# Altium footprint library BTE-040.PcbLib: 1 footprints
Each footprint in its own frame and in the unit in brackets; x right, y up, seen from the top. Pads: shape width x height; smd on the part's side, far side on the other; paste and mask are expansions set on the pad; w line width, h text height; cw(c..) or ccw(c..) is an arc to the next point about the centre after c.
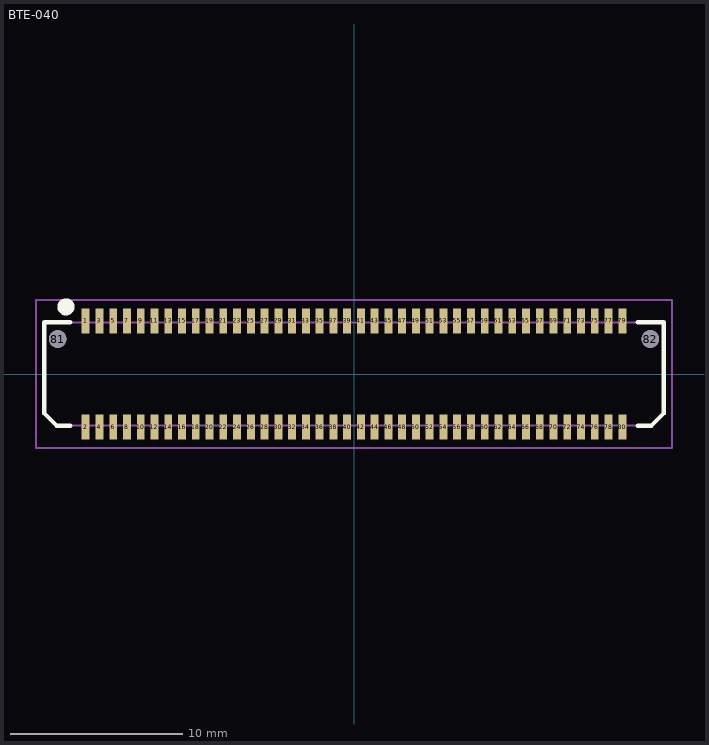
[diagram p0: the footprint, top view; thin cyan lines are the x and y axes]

## BTE-040 [mm] "0.8mm Samtech socket"
height 4.27
pads (82):
  rect 0.46x1.45 smd: 1(-15.6,3.085) 2(-15.6,-3.085) 3(-14.8,3.085) 4(-14.8,-3.085) 5(-14,3.085) 6(-14,-3.085) 7(-13.2,3.085) 8(-13.2,-3.085) 9(-12.4,3.085) 10(-12.4,-3.085) 11(-11.6,3.085) 12(-11.6,-3.085) 13(-10.8,3.085) 14(-10.8,-3.085) 15(-10,3.085) 16(-10,-3.085) 17(-9.2,3.085) 18(-9.2,-3.085) 19(-8.4,3.085) 20(-8.4,-3.085) 21(-7.6,3.085) 22(-7.6,-3.085) 23(-6.8,3.085) 24(-6.8,-3.085) 25(-6,3.085) 26(-6,-3.085) 27(-5.2,3.085) 28(-5.2,-3.085) 29(-4.4,3.085) 30(-4.4,-3.085) 31(-3.6,3.085) 32(-3.6,-3.085) 33(-2.8,3.085) 34(-2.8,-3.085) 35(-2,3.085) 36(-2,-3.085) 37(-1.2,3.085) 38(-1.2,-3.085) 39(-0.4,3.085) 40(-0.4,-3.085) 41(0.4,3.085) 42(0.4,-3.085) 43(1.2,3.085) 44(1.2,-3.085) 45(2,3.085) 46(2,-3.085) 47(2.8,3.085) 48(2.8,-3.085) 49(3.6,3.085) 50(3.6,-3.085) 51(4.4,3.085) 52(4.4,-3.085) 53(5.2,3.085) 54(5.2,-3.085) 55(6,3.085) 56(6,-3.085) 57(6.8,3.085) 58(6.8,-3.085) 59(7.6,3.085) 60(7.6,-3.085) 61(8.4,3.085) 62(8.4,-3.085) 63(9.2,3.085) 64(9.2,-3.085) 65(10,3.085) 66(10,-3.085) 67(10.8,3.085) 68(10.8,-3.085) 69(11.6,3.085) 70(11.6,-3.085) 71(12.4,3.085) 72(12.4,-3.085) 73(13.2,3.085) 74(13.2,-3.085) 75(14,3.085) 76(14,-3.085) 77(14.8,3.085) 78(14.8,-3.085) 79(15.6,3.085) 80(15.6,-3.085)
  round 1.02 hole 1.02 unplated: 81(-17.235,2.035) 82(17.235,2.035)
Top Overlay:
  circle w0.5: c-16.75,3.9 r0.25
  lines w0.254: -16.5,-3 -17.3,-3 -18,-2.3 -18,3 -16.5,3 ; 16.5,-3 17.3,-3 18,-2.3 18,3 16.5,3
Mechanical 15:
  lines w0.12: -18.5,-4.3 18.5,-4.3 18.5,4.3 -18.5,4.3 -18.5,-4.3
Mechanical 29:
  lines w0.127: -18,-2.25 -17.25,-3 17.25,-3 18,-2.25 18,3 -18,3 -18,-2.25
  text ".Designator" at -3.666,-0.494 h1.27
